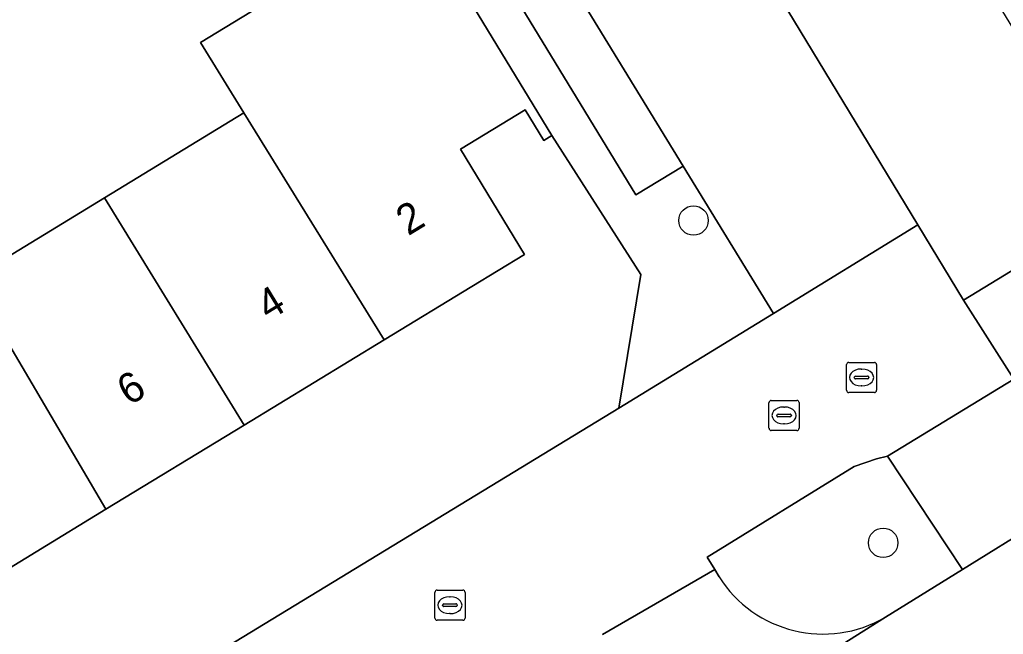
# Model space of a CAD drawing. Extents: x 157767 to 159172, y 387839 to 389425.
# Drawn here: x 158306.77 to 158339.4, y 388305.25 to 388325.64 of the extents above; entities that cross this region are included whole.
import ezdxf

# ---------------------------------------------------------------- set-up
doc = ezdxf.new("R2010")
doc.units = 0
for name, color, linetype in [('IMGEO_Boom', 7, 'Continuous'), ('IMGEO_Erf', 7, 'Continuous'), ('IMGEO_Fietspad_open', 7, 'Continuous'), ('IMGEO_Kolk', 7, 'Continuous'), ('IMGEO_Pand', 7, 'Continuous'), ('IMGEO_Pand_nummerreeks', 7, 'Continuous'), ('IMGEO_Parkeervlak_open', 7, 'Continuous'), ('IMGEO_Rijbaan_lokaal_gesloten', 7, 'Continuous'), ('IMGEO_Rijbaan_lokaal_open', 7, 'Continuous'), ('IMGEO_Rioolput', 7, 'Continuous'), ('IMGEO_Verkeerseiland_groen', 7, 'Continuous'), ('IMGEO_Voetpad_open', 7, 'Continuous')]:
    doc.layers.add(name, color=color, linetype=linetype)

msp = doc.modelspace()

# ---------------------------------------------------------------- linework, layer by layer
at = {"layer": 'IMGEO_Boom'}
for centre in [(158329.123, 388318.977), (158335.413, 388308.284)]:
    msp.add_circle(centre, 0.489, dxfattribs=at)
at = {"layer": 'IMGEO_Erf'}
msp.add_lwpolyline([(158334.235, 388334.362), (158331.423, 388338.976), (158328.599, 388343.609), (158325.682, 388348.394), (158320.536, 388345.274), (158336.567, 388318.836), (158338.084, 388316.334), (158350.888, 388324.146), (158350.38, 388324.98), (158342.778, 388320.347), (158339.867, 388325.123), (158337.039, 388329.763)], close=True, dxfattribs=at)
for points in [[(158276.015, 388301.615), (158280.763, 388304.507), (158285.393, 388307.327), (158286.442, 388305.638), (158286.546, 388305.701), (158291.133, 388308.495), (158295.741, 388311.301), (158300.357, 388314.113), (158305.131, 388317.02), (158309.582, 388319.731), (158314.207, 388322.548), (158312.761, 388324.887), (158317.166, 388327.569)], [(158302.653, 388298.156), (158326.649, 388312.756), (158327.37, 388317.188), (158324.424, 388321.803), (158324.151, 388321.636), (158323.532, 388322.653), (158321.388, 388321.347), (158323.515, 388317.854), (158321.764, 388316.788), (158318.861, 388315.02), (158314.215, 388312.19), (158309.628, 388309.396), (158304.99, 388306.572)]]:
    msp.add_lwpolyline(points, dxfattribs=at)
at = {"layer": 'IMGEO_Fietspad_open'}
msp.add_lwpolyline([(158335.562, 388311.158), (158338.044, 388307.393), (158340.574, 388308.966), (158339.785, 388310.258), (158394.137, 388343.439), (158393.034, 388346.31), (158339.745, 388313.717)], close=True, dxfattribs=at)
for points in [[(158329.968, 388307.16), (158329.827, 388307.397), (158326.105, 388305.237)], [(158327.728, 388304.268), (158329.232, 388301.865), (158335.487, 388305.815)]]:
    msp.add_lwpolyline(points, dxfattribs=at)
msp.add_arc((158333.422, 388309.339), 4.084, 212.2437, 300.3639, dxfattribs=at)
at = {"layer": 'IMGEO_Kolk'}
for p, q in [((158331.701, 388313.01), (158332.553, 388313.01)), ((158331.626, 388312.084), (158331.626, 388312.936)), ((158332.114, 388312.79), (158332.139, 388312.79)), ((158332.627, 388312.936), (158332.627, 388312.084)), ((158331.885, 388312.504), (158331.885, 388312.516)), ((158332.323, 388312.467), (158331.925, 388312.467)), ((158331.928, 388312.553), (158332.326, 388312.553)), ((158332.369, 388312.516), (158332.369, 388312.504)), ((158332.553, 388312.01), (158331.701, 388312.01)), ((158332.137, 388312.23), (158332.112, 388312.23)), ((158320.54, 388305.788), (158320.54, 388306.64)), ((158320.615, 388306.714), (158321.467, 388306.714)), ((158321.028, 388306.494), (158321.053, 388306.494)), ((158321.541, 388306.64), (158321.541, 388305.788)), ((158320.799, 388306.208), (158320.799, 388306.22)), ((158321.237, 388306.171), (158320.839, 388306.171)), ((158320.842, 388306.257), (158321.24, 388306.257)), ((158321.283, 388306.22), (158321.283, 388306.208)), ((158321.051, 388305.934), (158321.026, 388305.934)), ((158321.467, 388305.714), (158320.615, 388305.714))]:
    msp.add_line(p, q, dxfattribs=at)
for points in [[(158331.701, 388313.01), (158332.553, 388313.01)], [(158331.626, 388312.084), (158331.626, 388312.936)], [(158332.627, 388312.936), (158332.627, 388312.084)], [(158332.553, 388312.01), (158331.701, 388312.01)], [(158320.54, 388305.788), (158320.54, 388306.64)], [(158320.615, 388306.714), (158321.467, 388306.714)], [(158321.541, 388306.64), (158321.541, 388305.788)], [(158321.467, 388305.714), (158320.615, 388305.714)]]:
    msp.add_lwpolyline(points, dxfattribs=at)
for centre, radius, start, end in [((158331.703, 388312.934), 0.0765, 91.552, 178.448), ((158331.703, 388312.934), 0.0765, 91.552, 178.448), ((158332.551, 388312.934), 0.0765, 1.552, 88.448), ((158332.551, 388312.934), 0.0765, 1.552, 88.448), ((158331.925, 388312.513), 0.0403, 85.8775, 175.7526), ((158331.922, 388312.503), 0.0366, 178.938, 274.7102), ((158332.326, 388312.51), 0.043, 264.8664, 352.4533), ((158332.33, 388312.515), 0.0386, 1.7309, 96.639), ((158331.703, 388312.086), 0.0765, 181.552, 268.448), ((158331.703, 388312.086), 0.0765, 181.552, 268.448), ((158332.551, 388312.086), 0.0765, 271.552, 358.448), ((158332.551, 388312.086), 0.0765, 271.552, 358.448), ((158320.617, 388306.638), 0.0765, 91.552, 178.448), ((158320.617, 388306.638), 0.0765, 91.552, 178.448), ((158321.465, 388306.638), 0.0765, 1.552, 88.448), ((158321.465, 388306.638), 0.0765, 1.552, 88.448), ((158320.839, 388306.217), 0.0403, 85.8775, 175.7526), ((158320.836, 388306.207), 0.0366, 178.938, 274.7102), ((158321.24, 388306.214), 0.043, 264.8664, 352.4533), ((158321.244, 388306.219), 0.0386, 1.7309, 96.639), ((158320.617, 388305.79), 0.0765, 181.552, 268.448), ((158320.617, 388305.79), 0.0765, 181.552, 268.448), ((158321.465, 388305.79), 0.0765, 271.552, 358.448), ((158321.465, 388305.79), 0.0765, 271.552, 358.448)]:
    msp.add_arc(centre, radius, start, end, dxfattribs=at)
for centre, major_axis, ratio, start_param, end_param in [((158332.113, 388312.51), (-0.387, 0.002), 0.722429, 4.712389, 7.853982), ((158332.138, 388312.51), (-0.39, 0.002), 0.717154, 1.570796, 4.712389), ((158321.027, 388306.214), (-0.387, 0.002), 0.722429, 4.712389, 7.853982), ((158321.052, 388306.214), (-0.39, 0.002), 0.717154, 1.570796, 4.712389)]:
    msp.add_ellipse(centre, major_axis=major_axis, ratio=ratio, start_param=start_param, end_param=end_param, dxfattribs=at)
at = {"layer": 'IMGEO_Pand'}
for points in [[(158319.098, 388330.549), (158318.825, 388330.382), (158319.626, 388329.067), (158317.166, 388327.569), (158312.761, 388324.887), (158314.207, 388322.548), (158318.861, 388315.02), (158321.764, 388316.788), (158323.515, 388317.854), (158321.388, 388321.347), (158323.532, 388322.653), (158324.151, 388321.636), (158324.424, 388321.803)], [(158314.207, 388322.548), (158309.582, 388319.731), (158314.215, 388312.19), (158318.861, 388315.02)], [(158309.628, 388309.396), (158314.215, 388312.19), (158309.582, 388319.731), (158305.131, 388317.02)], [(158305.131, 388317.02), (158300.357, 388314.113), (158304.99, 388306.572), (158309.628, 388309.396)]]:
    msp.add_lwpolyline(points, close=True, dxfattribs=at)
at = {"layer": 'IMGEO_Parkeervlak_open'}
msp.add_lwpolyline([(158328.783, 388320.779), (158319.326, 388336.236), (158317.793, 388335.287), (158327.208, 388319.833)], close=True, dxfattribs=at)
at = {"layer": 'IMGEO_Rijbaan_lokaal_gesloten'}
msp.add_lwpolyline([(158340.574, 388308.966), (158338.044, 388307.393), (158335.487, 388305.815), (158329.232, 388301.865), (158325.841, 388299.724), (158323.243, 388298.097), (158319.303, 388295.635), (158318.479, 388295.12), (158316.732, 388294.034), (158307.259, 388288.147), (158296.76, 388281.603), (158293.929, 388279.825), (158284.109, 388273.656), (158271.906, 388265.997), (158262.426, 388260.118), (158253.604, 388254.566), (158246.245, 388250), (158242.941, 388247.95), (158240.03, 388246.171), (158235.601, 388243.333), (158222.599, 388235.192), (158221.83, 388234.711)], dxfattribs=at)
at = {"layer": 'IMGEO_Rijbaan_lokaal_open'}
msp.add_lwpolyline([(158306.538, 388368.361), (158301.543, 388365.303), (158305.556, 388358.744), (158313.03, 388346.527), (158319.326, 388336.236), (158328.783, 388320.779), (158331.773, 388315.892), (158336.567, 388318.836), (158320.536, 388345.274), (158319.356, 388347.221)], close=True, dxfattribs=at)
for points in [[(158329.827, 388307.397), (158329.58, 388307.813), (158334.451, 388310.816), (158335.188, 388311.069), (158335.562, 388311.158), (158339.745, 388313.717), (158338.084, 388316.334), (158336.567, 388318.836), (158331.773, 388315.892), (158326.649, 388312.756), (158302.653, 388298.156), (158305.681, 388293.117), (158314.034, 388298.249), (158316.619, 388299.808), (158319.186, 388301.356)], [(158326.105, 388305.237), (158329.827, 388307.397)]]:
    msp.add_lwpolyline(points, dxfattribs=at)
at = {"layer": 'IMGEO_Rioolput'}
for p, q in [((158334.272, 388314.27), (158335.124, 388314.27)), ((158334.197, 388313.344), (158334.197, 388314.196)), ((158334.685, 388314.05), (158334.71, 388314.05)), ((158335.198, 388314.196), (158335.198, 388313.344)), ((158334.456, 388313.764), (158334.456, 388313.776)), ((158334.894, 388313.727), (158334.496, 388313.727)), ((158334.499, 388313.813), (158334.897, 388313.813)), ((158334.94, 388313.776), (158334.94, 388313.764)), ((158335.124, 388313.27), (158334.272, 388313.27)), ((158334.708, 388313.49), (158334.683, 388313.49))]:
    msp.add_line(p, q, dxfattribs=at)
for points in [[(158334.272, 388314.27), (158335.124, 388314.27)], [(158334.197, 388313.344), (158334.197, 388314.196)], [(158335.198, 388314.196), (158335.198, 388313.344)], [(158335.124, 388313.27), (158334.272, 388313.27)]]:
    msp.add_lwpolyline(points, dxfattribs=at)
for centre, radius, start, end in [((158334.274, 388314.194), 0.0765, 91.552, 178.448), ((158334.274, 388314.194), 0.0765, 91.552, 178.448), ((158335.122, 388314.194), 0.0765, 1.552, 88.448), ((158335.122, 388314.194), 0.0765, 1.552, 88.448), ((158334.496, 388313.773), 0.0403, 85.8775, 175.7526), ((158334.493, 388313.763), 0.0366, 178.938, 274.7102), ((158334.897, 388313.77), 0.043, 264.8664, 352.4533), ((158334.901, 388313.775), 0.0386, 1.7309, 96.639), ((158334.274, 388313.346), 0.0765, 181.552, 268.448), ((158334.274, 388313.346), 0.0765, 181.552, 268.448), ((158335.122, 388313.346), 0.0765, 271.552, 358.448), ((158335.122, 388313.346), 0.0765, 271.552, 358.448)]:
    msp.add_arc(centre, radius, start, end, dxfattribs=at)
for centre, major_axis, ratio, start_param, end_param in [((158334.684, 388313.77), (-0.387, 0.002), 0.722429, 4.712389, 7.853982), ((158334.709, 388313.77), (-0.39, 0.002), 0.717154, 1.570796, 4.712389)]:
    msp.add_ellipse(centre, major_axis=major_axis, ratio=ratio, start_param=start_param, end_param=end_param, dxfattribs=at)
at = {"layer": 'IMGEO_Verkeerseiland_groen'}
for points in [[(158335.562, 388311.158), (158335.188, 388311.069), (158334.451, 388310.816), (158329.58, 388307.813), (158329.827, 388307.397), (158329.968, 388307.16)], [(158335.487, 388305.815), (158338.044, 388307.393), (158335.562, 388311.158)]]:
    msp.add_lwpolyline(points, dxfattribs=at)
msp.add_arc((158333.422, 388309.339), 4.084, 212.2437, 300.3639, dxfattribs=at)
at = {"layer": 'IMGEO_Voetpad_open'}
for points in [[(158313.03, 388346.527), (158311.426, 388345.565), (158303.994, 388357.753), (158305.556, 388358.744), (158301.543, 388365.303), (158298.895, 388363.783), (158306.661, 388351.075), (158312.502, 388341.518), (158312.755, 388341.098), (158313.595, 388339.7), (158313.609, 388339.677), (158319.098, 388330.549), (158324.424, 388321.803), (158327.37, 388317.188), (158326.649, 388312.756), (158331.773, 388315.892), (158328.783, 388320.779), (158327.208, 388319.833), (158317.793, 388335.287), (158319.326, 388336.236)], [(158393.034, 388346.31), (158392.115, 388348.703), (158387.771, 388346.651), (158377.558, 388340.419), (158368.226, 388334.726), (158362.339, 388331.133), (158353.847, 388325.951), (158350.888, 388324.146), (158338.084, 388316.334), (158339.745, 388313.717)]]:
    msp.add_lwpolyline(points, close=True, dxfattribs=at)

# ---------------------------------------------------------------- texts
at = {"layer": 'IMGEO_Pand_nummerreeks'}
for s, rotation, p in [('2', 31.3408, (158319.653, 388318.452)), ('4', 31.343, (158315.026, 388315.634)), ('6', 31.343, (158310.397, 388312.815))]:
    msp.add_text(s, height=1, rotation=rotation, dxfattribs=at).set_placement(p)

doc.saveas('drawing.dxf')
